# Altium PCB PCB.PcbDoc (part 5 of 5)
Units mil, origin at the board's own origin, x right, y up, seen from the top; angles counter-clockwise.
Board outline 6700 x 6500 mil, 2 copper layers (Top Layer, Bottom Layer); 203 components, 278 nets, 1296 pads, 461 vias.
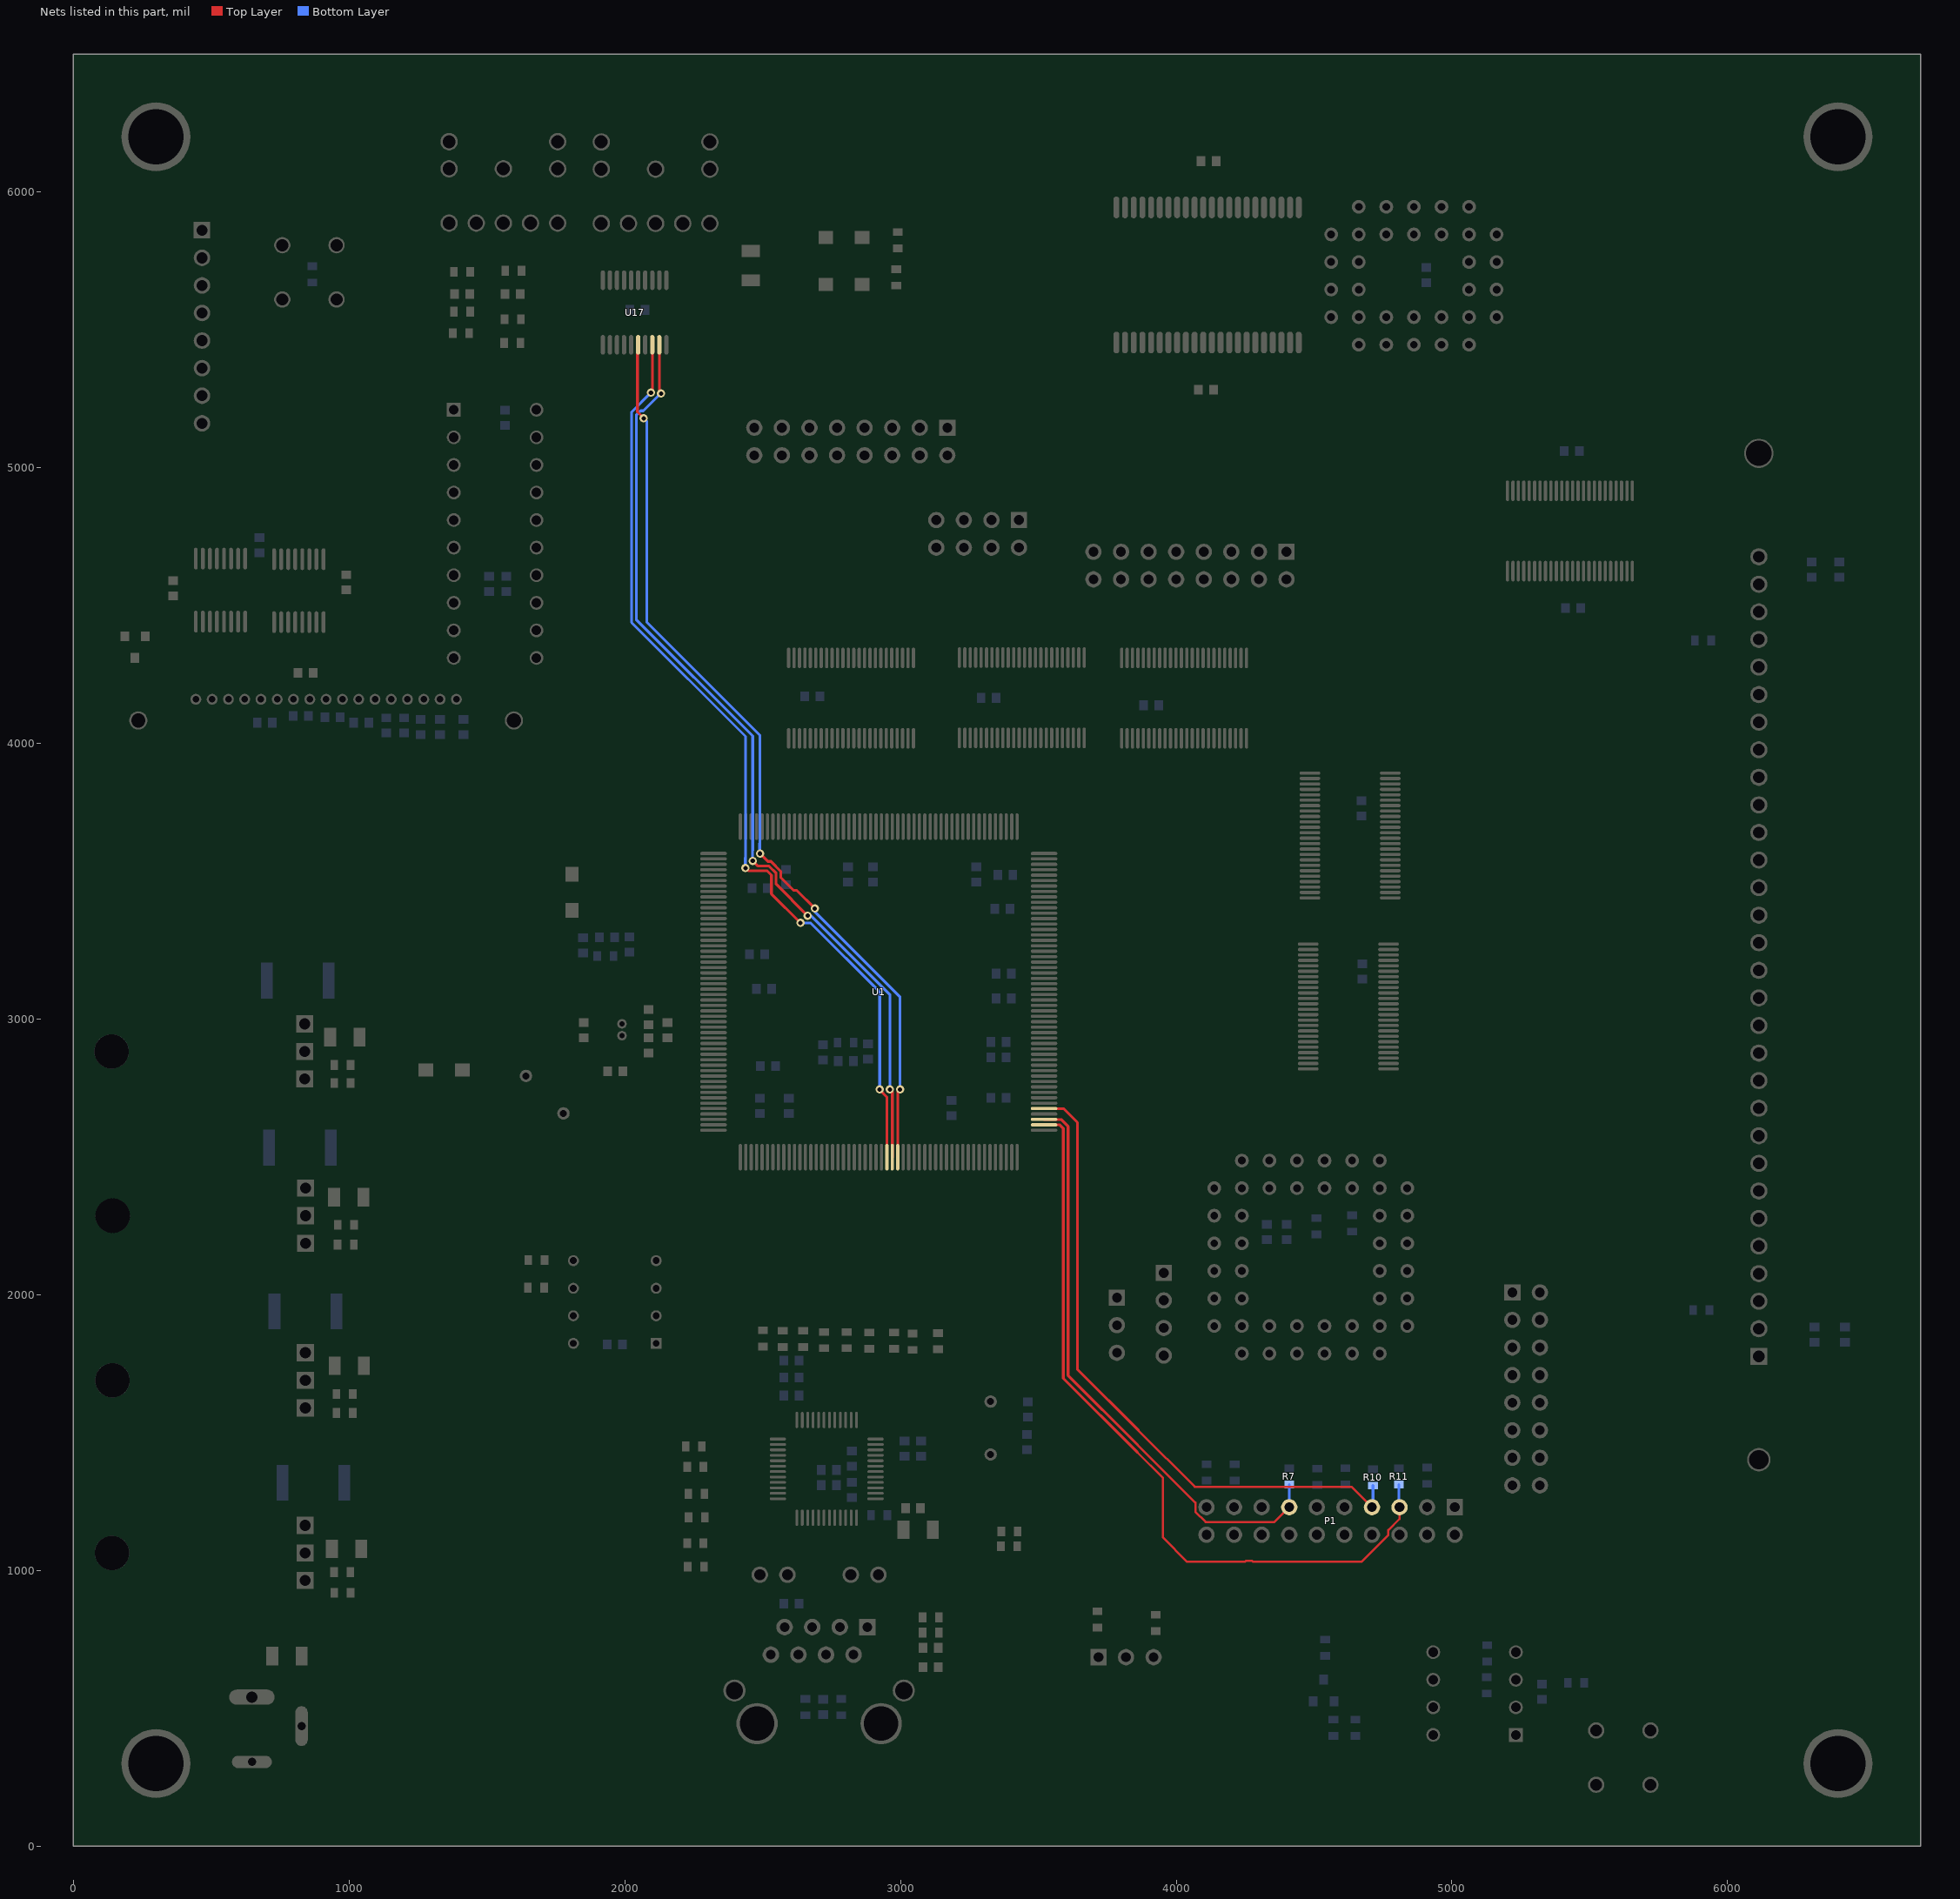
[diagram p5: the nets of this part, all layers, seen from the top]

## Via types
v1: diameter 30, hole 16, Top Layer to Bottom Layer, 461 vias

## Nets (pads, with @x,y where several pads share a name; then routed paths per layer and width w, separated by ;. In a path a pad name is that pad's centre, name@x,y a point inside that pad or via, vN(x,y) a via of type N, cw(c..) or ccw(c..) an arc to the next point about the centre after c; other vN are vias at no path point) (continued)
TD0: U1.82 U17.16 | length 3359.6
  Top Layer w10: U17.16@2048.77,5445.75 2046,5442.98 2046,5202.32 v1(2069,5179.32) ; v1(2490.46,3600.46) 2518.92,3572 2530.27,3572 2566,3536.27 2566,3513.77 2612.77,3467 2623.92,3467 v1(2689.46,3401.46) ; U1.82@2990.08,2499.41 2990.08,2736.34 v1(2998.74,2745)
  Bottom Layer w10: v1(2069,5179.32) 2080.32,5168 2080.32,4438.85 2490.46,4028.7 2490.46,3638.64 2489.62,3637.81 2489.62,3601.3 v1(2490.46,3600.46) ; v1(2689.46,3401.46) 2689.46,3389.22 2998.74,3079.94 v1(2998.74,2745)
TDI: P1.5 R11.1 U1.106 | length 2807.2
  Top Layer w8: 3858.68,1429.16 3952,1335.84 3952,1120 4040,1032 4249.23,1032 4253.23,1036 4274.77,1036 4278.77,1032 4672,1032 4769.47,1129.47 4769.47,1146.79 4810,1187.31 P1.5@4810,1230
  Top Layer w10: U1.106@3520.59,2616.54 3578.17,2616.54 3590.82,2603.89 3590.82,1697.02 3858.68,1429.16
  Bottom Layer w10: R11.1@4808,1312.47 4808,1232 P1.5@4810,1230
TDO: P1.13 R7.1 U1.107 | length 2147.4
  Top Layer w8: 3859.52,1456.16 4069.47,1246.21 4069.47,1213.21 4106.69,1176 4356,1176 P1.13@4410,1230
  Top Layer w10: U1.107@3520.59,2636.22 3582.53,2636.22 3607.82,2610.93 3607.82,1707.86 3859.52,1456.16
  Bottom Layer w10: P1.13@4410,1230 R7.1@4410,1312.47
TF0: U1.80 U17.18 | length 3423.7
  Top Layer w10: v1(2095,5272) 2101,5278 2101,5444.7 U17.18@2099.95,5445.75 ; v1(2438.13,3548.13) 2448.27,3538 2516.18,3538 2532,3522.18 2532,3454.27 v1(2637.13,3349.13) ; v1(2924.74,2745) 2924.74,2743.82 2950.71,2717.84 U1.80@2950.71,2499.41
  Bottom Layer w10: v1(2095,5272) 2025,5202 2025,4438.49 2438.13,4025.35 2438.13,3586.32 2437.3,3585.48 2437.3,3548.97 v1(2438.13,3548.13) ; v1(2637.13,3349.13) 2637.97,3348.3 2674.7,3348.3 2924.74,3098.26 v1(2924.74,2745)
TK0: U1.81 U17.19 | length 3415.9
  Top Layer w10: U17.19@2125.54,5445.75 2125.54,5281.46 2135,5272 v1(2132,5269) ; v1(2464.3,3574.3) 2483.59,3555 2523.23,3555 2549,3529.23 2549,3489.59 v1(2663.3,3375.3) ; v1(2961.74,2745) 2970.39,2736.34 U1.81@2970.39,2499.41
  Bottom Layer w10: v1(2132,5269) 2122,5269 2122,5260.82 2067.5,5206.32 2057.82,5206.32 2042,5190.5 2042,4449.32 2464.3,4027.03 2464.3,3612.48 2463.46,3611.64 2463.46,3575.13 v1(2464.3,3574.3) ; v1(2663.3,3375.3) 2675.54,3375.3 2961.74,3089.1 v1(2961.74,2745)
TMS: P1.7 R10.1 U1.109 | length 2392.9
  Top Layer w8: 3862.87,1508.49 4067.36,1304 4636,1304 P1.7@4710,1230
  Top Layer w10: U1.109@3520.59,2675.59 3591.24,2675.59 3641.82,2625.02 3641.82,1729.54 3862.87,1508.49
  Bottom Layer w10: P1.7@4710,1230 4714,1234 R10.1@4714,1308.47
pads on no net: J1. J1.7 J2. J2.B J2.C J3. J3.B J3.C J4.SWITCH P1.2 P6.11 P6.13 P6.15 REG_1V8.0 REG_3V3.0 REG_3V.0 REG_5V.0 SW_HangUp.3 SW_HangUp.4 SW_RESET.3 SW_RESET.4 U1.2 U1.15 U1.16 U1.17 U1.18 U1.21 U1.22 U1.23 U1.24 U1.42 U1.61 U1.64 U1.65 U1.66 U1.67 U1.68 U1.69 U1.73 U1.74 U1.77 U1.78 U1.79 U1.84 U1.85 U1.86 U1.87 U1.88 U1.89 U1.90 U1.91 U1.102 U1.103 U1.104 U1.118 U1.119 U1.120 U1.121 U1.123 U1.124 U1.125 U1.126 U1.127 U1.128 U1.144 U1.158 U1.159 U1.160 U1.161 U1.162 U1.163 U1.173 U1.174 U1.175 U1.176 U1.177 U1.178 U1.201 U1.202 U1.203 U1.204 U1.205 U1.206 U1.207 U1.208 U3.6 U3.8 U5.2 U5.30 U5.31 U5.32 U6.22 U6.23 U6.28 U8.6 U8.43 U9.12 U9.13 U9.14 U11.3 U11.4 U11.5 U11.6 U11.12 U13.1 U16.8 U16.9 U16.10 U16.11 U16.12 U16.25 U18.13 U18.14 U18.16 U18.17 U18.19 U18.20 U18.22 U18.23 U18.26 U18.27 U18.29 U18.30 U18.32 U18.33 U18.35 U18.36 U19.16 U19.17 U19.19 U19.20 U19.22 U19.23 U20. U20.19 U20.24 U20.26 U20.28 U20.29 U21.16 U21.17 U21.19 U21.20 U21.22 U21.23

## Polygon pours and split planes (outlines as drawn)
GND on Bottom Layer "Bottom Layer - GND" (solid, remove dead copper, pour order 0): 2161,203 2165,199 2980,199 2980,202 3328,550 3328,1143 3362,1143 3613,1394 3613,1783 3512,1783 3229,2066 2319,2066 2183,1930 2183,1457 2161,1360 2161,1283
GNDOSC on Bottom Layer "Bottom Layer-GNDOSC" (solid, remove dead copper, pour order 2): 1827,2463 1816,2474 1691,2474 1626,2539 1626,2608 1510,2724 1510,2974 1629,3093 2144,3093 2189,3048 2189,2824 2100,2735
GNDPLL on Bottom Layer "Bottom Layer-GNDPLL" (solid, remove dead copper, pour order 4): 2681.84,2806 2915,2806 2915,2951 2897,2951 2890,2951 2684,2951
GNDPLL on Bottom Layer "Bottom Layer-GNDPLL" (solid, remove dead copper, pour order 6): 1774,3179 2088,3179 2088,3348 1776,3348 1775,3349

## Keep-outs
Keep-Out Layer:
  the board outline again, w10

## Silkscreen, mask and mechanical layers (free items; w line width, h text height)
Bottom Overlay:
  text "EE 52 Will Werst Rev. 1.0" at 6205,6398 h80 r180
Mechanical 15:
  lines w50: -30,150 -30,-30 140,-30 ; -30,6360 -30,6530 150,6530 ; 6550,-30 6730,-30 6730,140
